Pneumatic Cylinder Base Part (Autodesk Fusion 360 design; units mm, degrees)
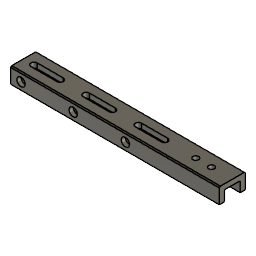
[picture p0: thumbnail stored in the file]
part number: 2025-12-15-10-30-58-806
sketch "Sketch1" plane through (0, 0, 0) normal (0, 0, 1) x axis (1, 0, 0)
  line L1 (-100, -12.5) -> (100, -12.5)
  line L2 (-100, 12.5) -> (-100, -12.5)
  line L3 (100, 12.5) -> (-100, 12.5)
  line L4 (100, -12.5) -> (100, 12.5)
  line L5 (-100, 12.5) -> (100, -12.5)
  line L6 (100, 12.5) -> (-100, -12.5)
  line L7 (0, -12.5) -> (0, 12.5)
  circle C1 centre (65, 0) radius 2.75
  circle C2 centre (80, 0) radius 2.75
  point P6 (0, 0)
  point P1 (0, 0)
  point P7 (65, 0)
  point P8 (80, 0)
  point P9 (0, 12.5)
  point P10 (0, -12.5)
  point P4 (-100, 12.5)
  point P5 (100, 12.5)
  point P3 (-100, -12.5)
  horizontal L1
  perpendicular L1 L2
  parallel L1 L3
  parallel L2 L4
  coincident L5 P6
  coincident L6 P6
  coincident P1 P6
  equal C1 C2
  horizontal P1 P7
  horizontal P6 P8
  midpoint L3 P9
  perpendicular L3 L7
  midpoint L1 P10
  dimension "d3" distance P4 P5 = 200
  dimension "d4" distance P3 P4 = 25
  dimension "d5" diameter C1 = 5.5
  dimension "d7" distance P7 P8 = 15
  dimension "d8" distance L4 P8 = 20
extrude "Extrude1" new body sketch "Sketch1" profile of L1 L2 L3 L4 C1 C2 along normal blind 5
sketch "Sketch2" plane through (100, 0, 0) normal (1, 0, 0) x axis (0, 1, 0)
  line L1 (12.5, 0) -> (-12.5, 0)
  line L2 (12.5, 5) -> (12.5, 0)
  line L3 (-12.5, 5) -> (12.5, 5)
  line L4 (-12.5, 0) -> (-12.5, 5)
  line L5 (-7.5, 0) -> (-12.5, 0)
  line L6 (-7.5, -10) -> (-7.5, 0)
  line L7 (-12.5, -10) -> (-7.5, -10)
  line L8 (-12.5, 0) -> (-12.5, -10)
  line L9 (12.5, -10) -> (12.5, 0)
  line L10 (7.5, -10) -> (12.5, -10)
  line L11 (7.5, 0) -> (7.5, -10)
  point P2 (-12.5, 0)
  point P6 (-12.5, 0)
  point P3 (12.5, 0)
  point P10 (12.5, 0)
  point P13 (7.5, 0)
  point P7 (-7.5, 0)
  point P9 (-12.5, -10)
  horizontal L5
  vertical L6
  horizontal L7
  vertical L8
  coincident P2 P6
  coincident P3 P10
  perpendicular L1 L9
  perpendicular L9 L10
  coincident L1 P13
  perpendicular L10 L11
  equal L7 L10
  collinear L7 L10
  dimension "d11" distance P6 P7 = 5
  dimension "d12" distance P6 P9 = 10
extrude "Extrude2" add sketch "Sketch2" profile of L1 L5 L6 L7 L8 L9 L10 L11 to an object
chamfer "Chamfer1" distance 1
fillet "Fillet1" radius 1
sketch "Sketch3" plane through (0, -12.5, 0) normal (0, -1, 0) x axis (1, 0, 0)
  line L1 (-100, 4) -> (100, 4)
  line L2 (-100, -10) -> (-100, 4)
  line L3 (100, -10) -> (-100, -10)
  line L4 (100, 4) -> (100, -10)
  line L5 (-90, -10) -> (-90, 4)
  point P6 (-90, 4)
  point P7 (-90, -10)
  point P8 (-90, -3)
  coincident L1 P6
  coincident L3 P7
  perpendicular L3 L5
  midpoint L5 P8
  dimension "d18" distance L2 L5 = 10
hole "Hole1" HoleDiameter 3 TipAngle 180 CBDepth 4 CBDiameter 8
work_plane "WorkPlane1" AlongDistance -10
sketch "Sketch4" plane through (-90, 0, 0) normal (-1, 0, 0) x axis (0, -1, 0)
  line L1 (-12.5, -4.5) -> (-7.5, -4.5)
  line L2 (-12.5, -10) -> (-12.5, -4.5)
  line L3 (-7.5, -10) -> (-12.5, -10)
  line L4 (8.5, -4.5) -> (8.5, -7)
  line L5 (7.5, -4.5) -> (8.5, -4.5)
  line L6 (12.5, -10) -> (7.5, -10)
  line L7 (12.5, -7) -> (12.5, -10)
  line L8 (8.5, -7) -> (12.5, -7)
  line L9 (-12.5, 4) -> (-11.5, 5)
  line L10 (-12.5, -1.5) -> (-12.5, 4)
  line L11 (-7.5, -1.5) -> (-12.5, -1.5)
  line L12 (6.5, 0) -> (-6.5, 0)
  line L13 (8.5, -1.5) -> (7.5, -1.5)
  line L14 (8.5, 1) -> (8.5, -1.5)
  line L15 (12.5, 1) -> (8.5, 1)
  line L16 (12.5, 4) -> (12.5, 1)
  line L17 (11.5, 5) -> (12.5, 4)
  line L18 (-11.5, 5) -> (11.5, 5)
  line L19 (-12.5, 4) -> (-11.5, 5)
  line L20 (-12.5, -10) -> (-12.5, 4)
  line L21 (-7.5, -10) -> (-12.5, -10)
  line L22 (-7.5, -1) -> (-7.5, -10)
  line L23 (6.5, 0) -> (-6.5, 0)
  line L24 (7.5, -10) -> (7.5, -1)
  line L25 (12.5, -10) -> (7.5, -10)
  line L26 (12.5, 4) -> (12.5, -10)
  line L27 (11.5, 5) -> (12.5, 4)
  line L28 (-11.5, 5) -> (11.5, 5)
  line L29 (-7.5, -4.5) -> (-7.5, -10)
  line L30 (7.5, -10) -> (7.5, -4.5)
  line L31 (-7.5, -1) -> (-7.5, -1.5)
  line L32 (7.5, -1.5) -> (7.5, -1)
  arc A1 centre (-6.5, -1) radius 1 clockwise from (-7.5, -1) to (-6.5, 0)
  arc A2 centre (6.5, -1) radius 1 clockwise from (6.5, 0) to (7.5, -1)
  arc A3 centre (-6.5, -1) radius 1 between (-6.5, 0) and (-7.5, -1)
  arc A4 centre (6.5, -1) radius 1 between (7.5, -1) and (6.5, 0)
sketch "Sketch5" plane through (0, 0, 5) normal (0, 0, 1) x axis (-1, 0, 0)
  line L1 (100, -11.5) -> (-100, -11.5)
  line L2 (100, 11.5) -> (100, -11.5)
  line L3 (-100, 11.5) -> (100, 11.5)
  line L4 (-100, -11.5) -> (-100, 11.5)
  line L5 (90, 0) -> (0, 0)
  line L6 (90, 0) -> (90, 12.5)
  line L7 (65, 3) -> (90, 3)
  line L8 (90, -3) -> (65, -3)
  line L9 (65, 0) -> (90, 0)
  circle C1 centre (-65, 0) radius 2.75
  circle C2 centre (-80, 0) radius 2.75
  arc A1 centre (65, 0) radius 3 clockwise from (65, -3) to (65, 3)
  arc A2 centre (90, 0) radius 3 clockwise from (90, 3) to (90, -3)
  point P1 (0, 0)
  point P9 (0, 0)
  point P8 (90, 12.5)
  point P10 (90, 12.5)
  point P17 (65, 0)
  point P11 (90, 0)
  point P16 (90, 0)
  coincident P1 P9
  perpendicular L2 L5
  coincident P8 P10
  perpendicular L1 L6
  tangent L7 A1
  tangent A1 L8
  parallel L7 L8
  tangent L8 A2
  tangent L7 A2
  coincident L5 P17
  perpendicular L6 L9
  coincident P11 P16
  dimension "d24" radius A2 = 3
  dimension "d25" distance P16 P17 = 25
extrude "Extrude3" cut sketch "Sketch5" profile of L7 A1 L8 A2 no distance stored
mirror "Mirror1" mirrorStitchTolerance 0.1
rectangular_pattern "R-Pattern1" uSpaceDistance 100 vSpaceDistance 0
